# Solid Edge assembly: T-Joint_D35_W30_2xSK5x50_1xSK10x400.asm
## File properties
Author: fknapp
Template: iso metric assembly.asm
Last saved by: fknapp
Revision: 6
Application: Solid Edge
Username: fknapp
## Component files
T-Joint_D35_W30.par
SK Schraube 5x50_ohne_Gewinde.par
SK Schraube 10x400_ohne_Gewinde_22042020.par
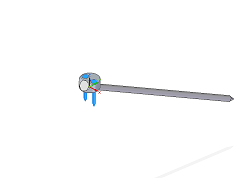
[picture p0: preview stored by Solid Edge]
